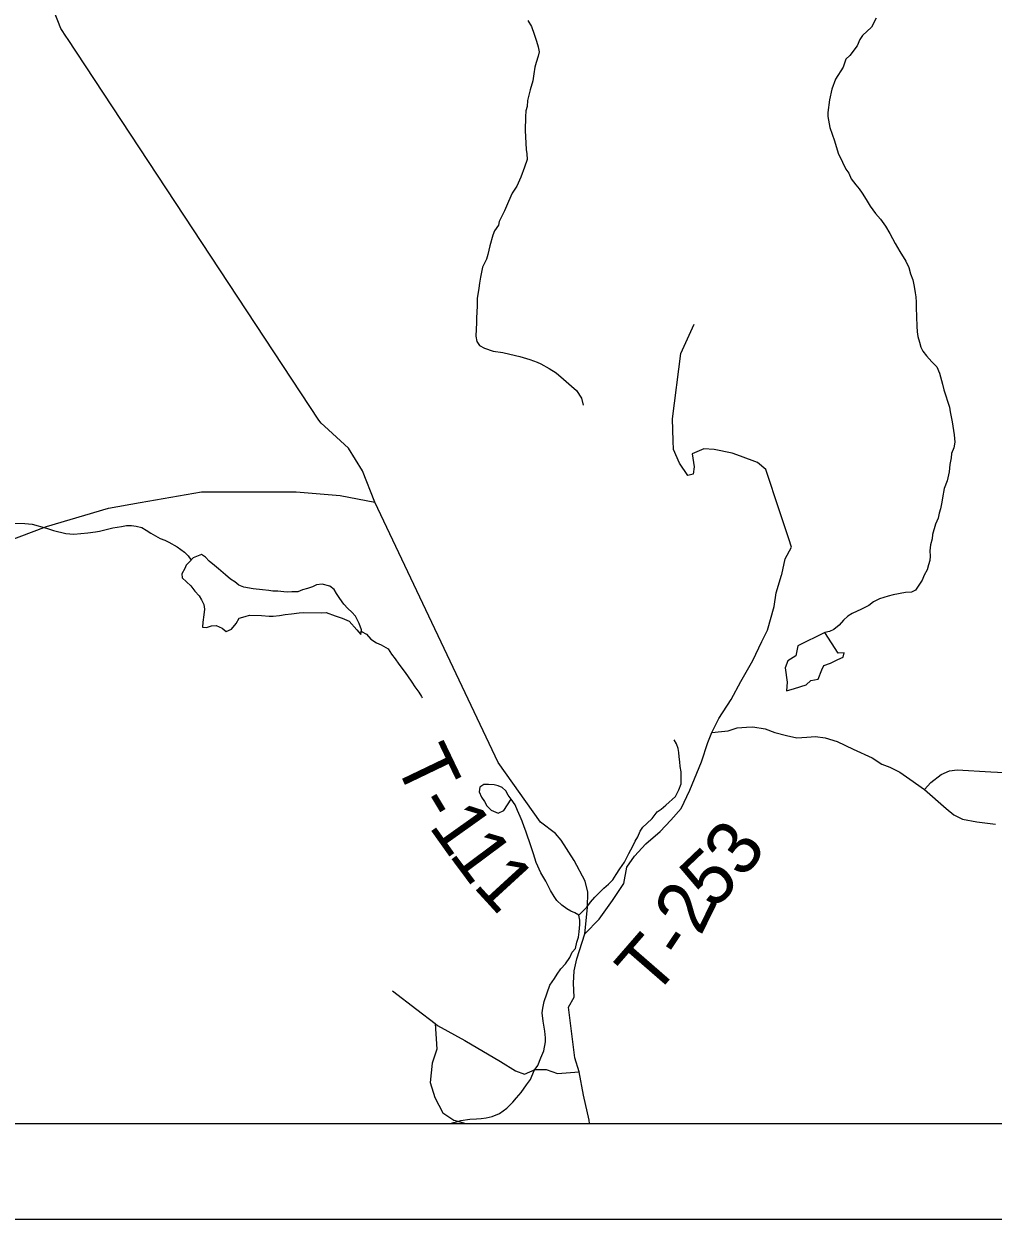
# Model space of a CAD drawing. Extents: x 0 to 34, y 0 to 22.
# Drawn here: x 6.659 to 7.671, y 14 to 15.248 of the extents above; entities that cross this region are included whole.
import ezdxf

# ---------------------------------------------------------------- set-up
doc = ezdxf.new("R2010")
doc.units = 0
for name, color, linetype in [('GM_X_Minor_Lake', 7, 'Continuous'), ('GM_X_Minor_River', 7, 'Continuous'), ('GM_X_Township_Road', 7, 'Continuous'), ('GM_X_Township_Road_Text', 7, 'Continuous'), ('SH_Data', 7, 'Continuous')]:
    doc.layers.add(name, color=color, linetype=linetype)

msp = doc.modelspace()

# ---------------------------------------------------------------- linework, layer by layer
at = {"layer": 'GM_X_Minor_Lake'}
for points in [[(7.4956, 14.6126), (7.4673, 14.5986), (7.4651, 14.5884), (7.4567, 14.5831), (7.4541, 14.5759), (7.456, 14.5607), (7.4556, 14.5516), (7.4639, 14.5543)], [(7.4639, 14.5543), (7.476, 14.5581), (7.481, 14.5626), (7.4885, 14.5641), (7.4923, 14.5736), (7.4946, 14.5781), (7.5014, 14.5808), (7.509, 14.5846), (7.5146, 14.5869), (7.5158, 14.5914), (7.5093, 14.591), (7.4956, 14.6126)]]:
    msp.add_lwpolyline(points, dxfattribs=at)
at = {"layer": 'GM_X_Minor_River'}
for points in [[(7.1852, 15.252), (7.1888, 15.2455), (7.1917, 15.2378), (7.1942, 15.2302), (7.196, 15.2245), (7.1971, 15.2191), (7.1959, 15.2146), (7.1939, 15.2082), (7.1926, 15.2033), (7.1914, 15.1961), (7.1905, 15.1889), (7.1877, 15.1794), (7.1848, 15.1684), (7.1843, 15.162), (7.1831, 15.1575), (7.1826, 15.1514), (7.1824, 15.137), (7.1826, 15.1305), (7.1835, 15.1172), (7.1842, 15.1126), (7.1845, 15.1069), (7.1817, 15.0986), (7.1777, 15.0884), (7.1738, 15.079), (7.1687, 15.0715), (7.1648, 15.0628), (7.1608, 15.053), (7.1553, 15.0421), (7.1545, 15.038), (7.1502, 15.0323), (7.1486, 15.0278), (7.1454, 15.0165), (7.1434, 15.0074), (7.1418, 15.0025), (7.1378, 14.9942), (7.1357, 14.984), (7.1345, 14.9775), (7.134, 14.9722), (7.1323, 14.9616), (7.1322, 14.9537), (7.1316, 14.9415), (7.1315, 14.9366), (7.1309, 14.9222), (7.1319, 14.9168), (7.1345, 14.9126), (7.1397, 14.9095), (7.1488, 14.9067), (7.159, 14.905), (7.1665, 14.9033), (7.1767, 14.9009), (7.1873, 14.8977), (7.1948, 14.8952), (7.1989, 14.8933), (7.2075, 14.8886), (7.2147, 14.8839), (7.2225, 14.8773), (7.2307, 14.87), (7.2359, 14.8653), (7.2411, 14.8576), (7.2429, 14.85)], [(7.5492, 15.2542), (7.5441, 15.2448), (7.5349, 15.2362), (7.5321, 15.2321), (7.5294, 15.2253), (7.5216, 15.2155), (7.5174, 15.2114), (7.5146, 15.2031), (7.5068, 15.1907), (7.5028, 15.1801), (7.5004, 15.1692), (7.4986, 15.1559), (7.4985, 15.1517), (7.5006, 15.1403), (7.5057, 15.1262), (7.5096, 15.1132), (7.514, 15.104), (7.5173, 15.0967), (7.5206, 15.0925), (7.5231, 15.0864), (7.528, 15.0802), (7.5313, 15.076), (7.5346, 15.0714), (7.5387, 15.0648), (7.5427, 15.0579), (7.5483, 15.0503), (7.5535, 15.0445), (7.559, 15.0372), (7.5634, 15.0295), (7.5689, 15.0191), (7.5737, 15.0107), (7.58, 15.0007), (7.5832, 14.9938), (7.585, 14.9874), (7.5876, 14.9809), (7.589, 14.974), (7.59, 14.9675), (7.5907, 14.9633), (7.5909, 14.9576), (7.5909, 14.9523), (7.5914, 14.9424), (7.5916, 14.9326), (7.5919, 14.9269), (7.5926, 14.9219), (7.5944, 14.9158), (7.5958, 14.9108), (7.598, 14.9066), (7.6017, 14.9016), (7.6073, 14.8955), (7.6125, 14.8901), (7.6154, 14.8836), (7.6186, 14.8721), (7.62, 14.866), (7.6258, 14.8481), (7.6264, 14.8431), (7.6285, 14.8328), (7.6305, 14.8191), (7.6312, 14.8115), (7.6303, 14.8055), (7.6279, 14.7998), (7.6275, 14.7952), (7.6262, 14.7881), (7.6253, 14.7805), (7.6233, 14.771), (7.6201, 14.7631), (7.6184, 14.7532), (7.6179, 14.7487), (7.6163, 14.7419), (7.6151, 14.7374), (7.6139, 14.7321), (7.6111, 14.7257), (7.6079, 14.7151), (7.6078, 14.7105), (7.6058, 14.7041), (7.6053, 14.698), (7.6056, 14.6923), (7.6051, 14.6878), (7.6039, 14.6832), (7.6023, 14.678), (7.5992, 14.6727), (7.5972, 14.6674), (7.5902, 14.6569), (7.586, 14.6547), (7.5799, 14.6544)], [(6.6468, 14.7268), (6.6596, 14.7266), (6.6672, 14.7257), (6.6823, 14.7217), (6.6894, 14.7193), (6.7023, 14.716), (6.7106, 14.7155), (6.7254, 14.7168), (6.7334, 14.7178), (6.7375, 14.7185), (6.7516, 14.722), (6.7607, 14.7234), (6.7657, 14.7244), (6.771, 14.7244), (6.7759, 14.7239), (6.7819, 14.7223), (6.7864, 14.7195), (6.7913, 14.7164), (6.801, 14.7109), (6.8059, 14.7093), (6.81, 14.707), (6.8187, 14.7023), (6.8262, 14.6965), (6.8303, 14.6926), (6.8332, 14.6882)], [(6.8442, 14.6468), (6.8464, 14.6418), (6.8471, 14.6372), (6.8466, 14.6312), (6.8457, 14.6236), (6.8452, 14.6183), (6.8494, 14.6178), (6.8547, 14.6196), (6.8593, 14.62), (6.8657, 14.6172), (6.8698, 14.6137), (6.8755, 14.6163), (6.8805, 14.6222), (6.8836, 14.6275), (6.8897, 14.6293), (6.8943, 14.6307), (6.9068, 14.6305), (6.9147, 14.6296), (6.9189, 14.6296), (6.9257, 14.6306), (6.9314, 14.6316), (6.9383, 14.6323), (6.9462, 14.6333), (6.9508, 14.6336), (6.9697, 14.6333), (6.9743, 14.6336), (6.9837, 14.63), (6.9912, 14.6276), (6.9984, 14.6244), (7.0065, 14.6155), (7.0106, 14.6105), (7.0115, 14.6155), (7.0089, 14.622), (7.0049, 14.6296), (7.0012, 14.6339), (6.9971, 14.6377), (6.993, 14.6424), (6.9886, 14.6481), (6.9852, 14.6535), (6.9827, 14.6577), (6.9782, 14.6612), (6.9703, 14.6632), (6.9642, 14.6626), (6.96, 14.6604), (6.955, 14.6586), (6.9497, 14.6571), (6.9447, 14.6553), (6.9387, 14.6551), (6.9341, 14.6548), (6.93, 14.6552), (6.9239, 14.6557), (6.9186, 14.6558), (6.9145, 14.6566), (6.908, 14.6571), (6.8982, 14.6584), (6.8884, 14.6601), (6.8831, 14.6621), (6.879, 14.6656), (6.8745, 14.6683), (6.8693, 14.6729), (6.8618, 14.6791), (6.8577, 14.6826), (6.8521, 14.6873), (6.8484, 14.6915), (6.8443, 14.6943), (6.8355, 14.6906), (6.8313, 14.6861), (6.8282, 14.6831)], [(6.8282, 14.6831), (6.8266, 14.6794), (6.8235, 14.6741), (6.8238, 14.6699), (6.8286, 14.6657), (6.8331, 14.6614), (6.8372, 14.656), (6.8416, 14.651), (6.8442, 14.6468)], [(7.5799, 14.6544), (7.567, 14.652), (7.5617, 14.6505), (7.5571, 14.6491), (7.5525, 14.648), (7.5464, 14.6447), (7.5414, 14.641), (7.5338, 14.637), (7.5239, 14.6326), (7.5196, 14.6296), (7.515, 14.6255), (7.5104, 14.6203), (7.505, 14.6158), (7.5004, 14.6136), (7.4956, 14.6126)], [(7.0113, 14.614), (7.0114, 14.6139), (7.0167, 14.6108), (7.0211, 14.6058), (7.0271, 14.6019), (7.032, 14.5999), (7.0391, 14.5956), (7.0428, 14.5902), (7.0465, 14.5852), (7.0502, 14.5795), (7.0558, 14.5722), (7.0595, 14.5676), (7.0639, 14.5607), (7.0672, 14.556), (7.0713, 14.5503), (7.0742, 14.5457), (7.0746, 14.5443)], [(7.2384, 14.3173), (7.2469, 14.3259), (7.2508, 14.3312), (7.255, 14.3364), (7.2646, 14.3457), (7.2693, 14.3498), (7.2739, 14.3543), (7.2774, 14.3599), (7.2813, 14.366), (7.286, 14.3727), (7.2907, 14.3817), (7.295, 14.3896), (7.2973, 14.3949), (7.3001, 14.3991), (7.3024, 14.4051), (7.3052, 14.4092), (7.3094, 14.4133), (7.3152, 14.4185), (7.3202, 14.4253), (7.3244, 14.4283), (7.3294, 14.4323), (7.3394, 14.4413), (7.343, 14.4484), (7.3453, 14.4545), (7.3455, 14.4617), (7.3452, 14.467), (7.3442, 14.4727), (7.3439, 14.4777), (7.3432, 14.483), (7.3429, 14.4872), (7.3422, 14.4917), (7.3404, 14.4963), (7.3382, 14.5005)], [(7.2083, 14.2442), (7.213, 14.2513), (7.2157, 14.2558), (7.2196, 14.2614), (7.2246, 14.2667), (7.2289, 14.2734), (7.2313, 14.2787), (7.2348, 14.2828), (7.2364, 14.2893), (7.238, 14.2945), (7.2388, 14.3002), (7.2394, 14.3078), (7.2394, 14.3124), (7.2384, 14.3173), (7.2343, 14.32), (7.2301, 14.3216), (7.226, 14.324), (7.2208, 14.3279), (7.2156, 14.3329), (7.2126, 14.3371), (7.2089, 14.3433), (7.2038, 14.3528), (7.1986, 14.3617), (7.1939, 14.3724), (7.191, 14.3815), (7.1871, 14.393), (7.1846, 14.401), (7.1831, 14.4052), (7.1813, 14.4098), (7.1791, 14.4155), (7.1773, 14.4205), (7.1744, 14.4266), (7.1719, 14.4327), (7.1678, 14.4385), (7.1645, 14.4427), (7.1623, 14.4473), (7.1582, 14.4508), (7.154, 14.4524), (7.1499, 14.4536), (7.1442, 14.4541), (7.1393, 14.4538), (7.1351, 14.4512), (7.1342, 14.4463), (7.1368, 14.4406), (7.1397, 14.4363), (7.1423, 14.4317), (7.1468, 14.4271), (7.1543, 14.4239), (7.16, 14.4269), (7.1678, 14.4385)], [(7.105, 14.1), (7.1062, 14.1005), (7.1107, 14.1015), (7.1153, 14.103), (7.1244, 14.1043), (7.1316, 14.1046), (7.1365, 14.1049), (7.1415, 14.1059), (7.1479, 14.107), (7.1556, 14.1103), (7.1633, 14.1158), (7.1694, 14.1222), (7.1733, 14.1267), (7.1783, 14.1323), (7.1838, 14.1402), (7.188, 14.1458), (7.1916, 14.1552), (7.1955, 14.1605), (7.1986, 14.1684), (7.2018, 14.1759), (7.2035, 14.185), (7.2036, 14.1892), (7.2029, 14.1964), (7.2012, 14.2067), (7.2002, 14.2154), (7.2007, 14.2204), (7.2023, 14.2272), (7.2083, 14.2442)]]:
    msp.add_lwpolyline(points, dxfattribs=at)
at = {"layer": 'GM_X_Township_Road'}
for points in [[(6.703, 15.2346), (6.6971, 15.2435), (6.6903, 15.2613), (6.6869, 15.2849), (6.6861, 15.3058), (6.6907, 15.3255), (6.69, 15.3441), (6.6797, 15.3658), (6.6718, 15.4022), (6.6604, 15.447)], [(6.9669, 14.8346), (6.7041, 15.233), (6.703, 15.2346)], [(7.3371, 14.8129), (7.3363, 14.8359), (7.3449, 14.9041), (7.359, 14.9347)], [(7.0251, 14.7489), (7.0123, 14.7817), (6.9979, 14.8052), (6.9727, 14.8281), (6.9691, 14.8314), (6.9669, 14.8346)], [(7.4505, 14.6734), (7.4541, 14.6897), (7.4608, 14.7017), (7.4578, 14.7106), (7.4464, 14.745), (7.4355, 14.7776), (7.4339, 14.7831), (7.425, 14.7901), (7.4072, 14.7968), (7.3987, 14.8001), (7.3797, 14.804), (7.3692, 14.8044), (7.3568, 14.7994), (7.3591, 14.7858), (7.3579, 14.7781), (7.3525, 14.7766), (7.3436, 14.7897), (7.3374, 14.804), (7.3371, 14.8129)], [(6.7801, 14.7484), (6.8441, 14.7597), (6.9432, 14.7597), (6.9889, 14.7559), (7.0251, 14.7489)], [(6.6117, 14.6969), (6.6822, 14.7235), (6.747, 14.7426), (6.7801, 14.7484)], [(7.2447, 14.298), (7.2475, 14.3254), (7.2478, 14.3415), (7.2451, 14.3528), (7.2334, 14.3746), (7.2198, 14.3959), (7.2139, 14.4027), (7.1985, 14.4147), (7.1541, 14.4769), (7.0251, 14.7489)], [(7.2447, 14.298), (7.2598, 14.3134), (7.2735, 14.3329), (7.2854, 14.3504), (7.2885, 14.3675), (7.2967, 14.3791), (7.3084, 14.3921), (7.3234, 14.4048), (7.3344, 14.4167), (7.3453, 14.4287), (7.3545, 14.4479), (7.3665, 14.4776), (7.3734, 14.4978), (7.3775, 14.5081), (7.3846, 14.5228), (7.3976, 14.5426), (7.4076, 14.5614), (7.4202, 14.5833), (7.4298, 14.6032), (7.4356, 14.6151), (7.4425, 14.6398), (7.4445, 14.6541), (7.4503, 14.6726), (7.4505, 14.6734)], [(7.3775, 14.5081), (7.3875, 14.5092), (7.3944, 14.51), (7.4039, 14.513), (7.4135, 14.5138), (7.4204, 14.5142), (7.433, 14.5119), (7.4433, 14.5081), (7.4555, 14.505), (7.4663, 14.5027), (7.4766, 14.5035), (7.4858, 14.5039), (7.4957, 14.5027), (7.5083, 14.4989), (7.5251, 14.4909), (7.545, 14.4817), (7.555, 14.4752), (7.5634, 14.4721), (7.5737, 14.4668), (7.5844, 14.4595), (7.5997, 14.4488), (7.6223, 14.4289), (7.6303, 14.4224), (7.6395, 14.4178), (7.6544, 14.4148), (7.6739, 14.4125)], [(7.5997, 14.4488), (7.6062, 14.4561), (7.6169, 14.4645), (7.6257, 14.4683), (7.6337, 14.4691), (7.6689, 14.4672), (7.6895, 14.466), (7.7102, 14.4645), (7.7366, 14.4633), (7.7614, 14.4626), (7.7818, 14.4621), (7.8021, 14.4597)], [(7.2497, 14.1), (7.2492, 14.1033), (7.2433, 14.1295), (7.2387, 14.1538), (7.2343, 14.1684), (7.2275, 14.2212), (7.2334, 14.2317), (7.2328, 14.2464), (7.2334, 14.2594), (7.2362, 14.272), (7.2447, 14.298)], [(7.0437, 14.2383), (7.0692, 14.219), (7.0883, 14.2042), (7.0908, 14.2023), (7.1193, 14.1867), (7.1565, 14.1646), (7.1724, 14.1548), (7.1815, 14.1513), (7.1929, 14.1563), (7.2043, 14.1563), (7.2161, 14.1521), (7.2387, 14.1538)], [(7.0883, 14.2042), (7.09, 14.1776), (7.0851, 14.1628), (7.0832, 14.1426), (7.0881, 14.1271), (7.0964, 14.1111), (7.1078, 14.1035), (7.1205, 14.1)]]:
    msp.add_lwpolyline(points, dxfattribs=at)
at = {"layer": 'SH_Data'}
for p, q in [((2.1, 14.1), (8.9, 14.1)), ((2, 14), (9, 14))]:
    msp.add_line(p, q, dxfattribs=at)

# ---------------------------------------------------------------- texts
at = {"layer": 'GM_X_Township_Road_Text'}
for s, rotation, p in [('T', 295.6158, (7.0452, 14.4776)), ('-', 301.0279, (7.0663, 14.4341)), ('1', 305.4214, (7.0809, 14.4101)), ('3', 53.6389, (7.4105, 14.3542)), ('1', 306.6852, (7.102, 14.3805)), ('5', 43.5868, (7.378, 14.322)), ('1', 312.4775, (7.1269, 14.3476)), ('2', 63.8715, (7.3657, 14.2948)), ('T', 49.0003, (7.3159, 14.23)), ('-', 56.0378, (7.3484, 14.2681))]:
    msp.add_text(s, height=0.0568, rotation=rotation, dxfattribs=at).set_placement(p)

doc.saveas('drawing.dxf')
